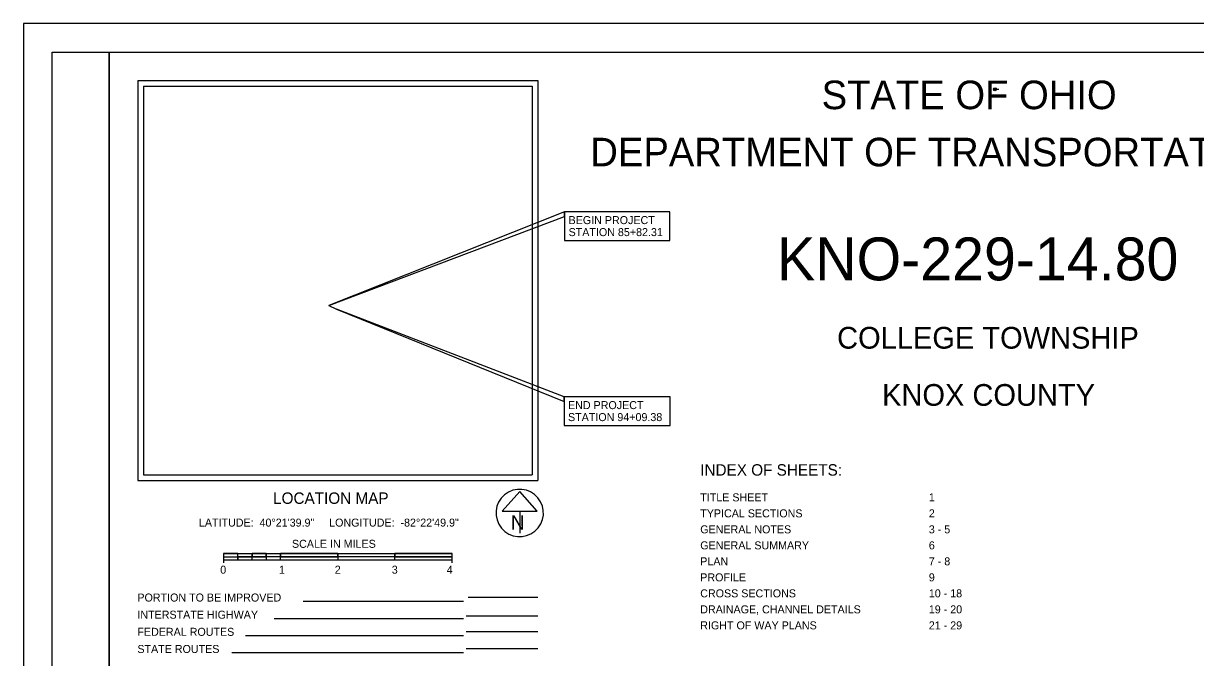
# Model space of a CAD drawing. Extents: x 0 to 84, y -106 to 22.
# Drawn here: x 0 to 20.51, y 10.9 to 22 of the extents above; entities that cross this region are included whole.
import ezdxf

# ---------------------------------------------------------------- set-up
doc = ezdxf.new("R2010")
doc.units = 0
for name, color, linetype in [('CS-ALGN-CNTR', 7, 'Continuous'), ('CS-ALGN-TEXT', 7, 'Continuous'), ('CS-ANNO', 7, 'Continuous'), ('CS-ANNO-MATC', 7, 'Continuous'), ('CS-ANNO-MATC-MASK', 7, 'Continuous')]:
    doc.layers.add(name, color=color, linetype=linetype)

msp = doc.modelspace()

# ---------------------------------------------------------------- linework, layer by layer
at = {"layer": 'CS-ALGN-CNTR'}
msp.add_lwpolyline([(0, 0), (34, 0), (34, 22), (0, 22)], close=True, dxfattribs=at)
at = {"layer": 'CS-ALGN-TEXT'}
for points in [[(0.5, 21.5), (1.5, 21.5), (1.5, 0.5), (0.5, 0.5)], [(1.5, 21.5), (33.5, 21.5), (33.5, 0.5), (1.5, 0.5)]]:
    msp.add_lwpolyline(points, close=True, dxfattribs=at)
at = {"layer": 'CS-ANNO'}
for p, q in [((2, 21), (9, 21)), ((2, 21), (2, 14)), ((9, 21), (9, 14)), ((2.1, 20.9), (2.1, 14.1)), ((2.1, 20.9), (8.9, 20.9)), ((8.9, 20.9), (8.9, 14.1)), ((2, 14), (9, 14)), ((2.1, 14.1), (8.9, 14.1)), ((8.685, 13.809), (8.377, 13.468)), ((8.992, 13.468), (8.685, 13.809)), ((8.377, 13.468), (8.992, 13.468)), ((8.685, 13.468), (8.685, 13.081)), ((8.685, 13.435), (8.685, 13.435)), ((8.685, 13.435), (8.685, 13.435)), ((7.783, 11.963), (9, 11.963)), ((7.7, 11.885), (4.894, 11.885)), ((7.7, 11.585), (4.39, 11.585)), ((9, 11.629), (7.75, 11.629)), ((7.7, 11.285), (3.885, 11.285)), ((9, 11.357), (7.75, 11.357)), ((7.7, 10.985), (3.645, 10.985)), ((9, 11.057), (7.75, 11.057))]:
    msp.add_line(p, q, dxfattribs=at)
msp.add_arc((8.685, 13.435), 0.415, 129.7798, 129.7633, dxfattribs=at)
at = {"layer": 'CS-ANNO-MATC'}
for p, q in [((5.343, 17.067), (5.477, 17.003)), ((3.5, 12.725), (3.5, 12.562)), ((3.5, 12.725), (7.5, 12.725)), ((3.75, 12.612), (3.75, 12.725)), ((4, 12.612), (4, 12.725)), ((4.25, 12.725), (4.25, 12.612)), ((4.5, 12.612), (4.5, 12.725)), ((5.5, 12.725), (5.5, 12.612)), ((6.5, 12.612), (6.5, 12.725)), ((7.5, 12.562), (7.5, 12.725)), ((3.5, 12.669), (3.75, 12.669)), ((3.5, 12.612), (7.5, 12.612)), ((3.75, 12.669), (4, 12.669)), ((4.25, 12.669), (4, 12.669)), ((4.5, 12.669), (4.25, 12.669)), ((5.5, 12.669), (4.5, 12.669)), ((6.5, 12.669), (5.5, 12.669)), ((7.5, 12.669), (6.5, 12.669))]:
    msp.add_line(p, q, dxfattribs=at)
for points in [[(5.343, 17.067), (9.47, 18.622), (9.47, 18.704)], [(9.47, 18.204), (11.311, 18.204), (11.311, 18.704), (9.47, 18.704)], [(5.477, 17.003), (9.46, 15.387), (9.46, 15.467)], [(9.46, 14.967), (11.315, 14.967), (11.315, 15.467), (9.46, 15.467)], [(3.5, 12.725), (3.5, 12.669), (3.75, 12.669), (3.75, 12.725)], [(4, 12.725), (4, 12.669), (4.25, 12.669), (4.25, 12.725)], [(4.5, 12.725), (4.5, 12.669), (5.5, 12.669), (5.5, 12.725)], [(7.5, 12.725), (6.5, 12.725), (6.5, 12.669), (7.5, 12.669)], [(3.75, 12.612), (4, 12.612), (4, 12.669), (3.75, 12.669)], [(4.25, 12.612), (4.5, 12.612), (4.5, 12.669), (4.25, 12.669)], [(5.5, 12.612), (6.5, 12.612), (6.5, 12.669), (5.5, 12.669)]]:
    msp.add_lwpolyline(points, close=True, dxfattribs=at)
at = {"layer": 'CS-ANNO-MATC-MASK'}
for p, q in [((16.974, 20.848), (17.026, 20.848)), ((17, 20.848), (17.072, 20.848))]:
    msp.add_line(p, q, dxfattribs=at)
msp.add_circle((17, 20.848), 0.026, dxfattribs=at)

# ---------------------------------------------------------------- texts
at = {"layer": 'CS-ANNO'}
msp.add_text('N', height=0.25, dxfattribs=at).set_placement((8.529, 13.144))
at = {"layer": 'CS-ANNO-MATC'}
for s, height, p in [('STATE OF OHIO', 0.5, (13.968, 20.5)), ('DEPARTMENT OF TRANSPORTATION', 0.5, (9.92, 19.5)), ('BEGIN PROJECT', 0.14, (9.54, 18.489)), ('STATION 85+82.31', 0.14, (9.54, 18.279)), ('KNO-229-14.80', 0.75, (13.187, 17.505)), ('COLLEGE TOWNSHIP', 0.38, (14.239, 16.31)), ('KNOX COUNTY', 0.38, (15.026, 15.31)), ('END PROJECT', 0.14, (9.53, 15.252)), ('STATION 94+09.38', 0.14, (9.53, 15.042)), ('INDEX OF SHEETS:', 0.2, (11.844, 14.088)), ('LOCATION MAP', 0.2, (4.369, 13.594)), ('TITLE SHEET                        ', 0.14, (11.844, 13.638)), ('1      ', 0.14, (15.844, 13.638)), ('LATITUDE:  40°21\'39.9"     LONGITUDE:  -82°22\'49.9"', 0.14, (3.071, 13.196)), ('TYPICAL SECTIONS                   ', 0.14, (11.844, 13.358)), ('2      ', 0.14, (15.844, 13.358)), ('GENERAL NOTES                      ', 0.14, (11.844, 13.078)), ('3 - 5', 0.14, (15.844, 13.078)), ('SCALE IN MILES', 0.14, (4.699, 12.825)), ('GENERAL SUMMARY                    ', 0.14, (11.844, 12.798)), ('6', 0.14, (15.844, 12.798)), ('0', 0.14, (3.444, 12.372)), ('1', 0.14, (4.471, 12.372)), ('2', 0.14, (5.448, 12.372)), ('3', 0.14, (6.446, 12.372)), ('4', 0.14, (7.408, 12.372)), ('PLAN                               ', 0.14, (11.844, 12.518)), ('7 - 8', 0.14, (15.844, 12.518)), ('PROFILE                            ', 0.14, (11.844, 12.238)), ('9', 0.14, (15.844, 12.238)), ('PORTION TO BE IMPROVED', 0.14, (1.994, 11.885)), ('CROSS SECTIONS                     ', 0.14, (11.844, 11.958)), ('10 - 18', 0.14, (15.844, 11.958)), ('INTERSTATE HIGHWAY', 0.14, (1.994, 11.585)), ('DRAINAGE, CHANNEL DETAILS           ', 0.14, (11.844, 11.678)), ('19 - 20', 0.14, (15.844, 11.678)), ('RIGHT OF WAY PLANS', 0.14, (11.844, 11.398)), ('21 - 29', 0.14, (15.844, 11.398)), ('FEDERAL ROUTES', 0.14, (1.994, 11.285)), ('STATE ROUTES', 0.14, (1.994, 10.985))]:
    msp.add_text(s, height=height, dxfattribs=at).set_placement(p)
at = {"layer": 'CS-ANNO-MATC-MASK'}
for s, p in [('2', (16.999, 20.854)), ('R/W Legend Sheet', (17.033, 20.854)), ('CUSTOM 1:2640', (17.033, 20.838))]:
    msp.add_text(s, height=0.00328, dxfattribs=at).set_placement(p)

doc.saveas('drawing.dxf')
